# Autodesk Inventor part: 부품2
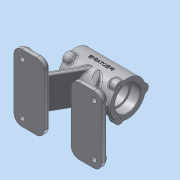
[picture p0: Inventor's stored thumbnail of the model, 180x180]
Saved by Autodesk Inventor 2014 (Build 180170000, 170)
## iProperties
Created: 2026-04
Part Number: 부품2
Material: 알루미늄 6061
Document SubType Name: Modeling
Designer: dg
Density: 2.71 g/cm^3
Appearance: 알루미늄 - 평지
Mass: 749.292 g
Surface Area: 672.069 cm^2
Volume: 276.492 cm^3
Author: dg
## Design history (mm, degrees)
sketch "스케치1"
  geometry: L1 (0, 0)-(-43, 0); L2 (0, 0)-(43, 0); L3 (-43, 0)-(-43, 29); L4 (43, 0)-(43, 29); L5 (-43, 0)-(43, 0); L6 (-43, 29)-(43, 29)
  constraints: 12 end point, 2 collinear, 1 horizontal, 1 perpendicular
  dimensions: "d20" = 43 distance from line of L3 L1.start; "d21" = 43 distance from line of L4 L1.start; "d22" = 58 diameter of L6 L1
revolve "회전3" stored, may be unused: angle "d23" = 90 deg
sketch "스케치4"
  geometry: L1 (0, 0)-(0, 37.954); L2 (0, 23.727)-(-6, 23.727); L3 (-6, 23.727)-(-6, 32); L4 (-6, 32)-(0, 32); L5 (0, 32)-(0, 23.727); L6 (-43, 29)-(43, 29) reference
  constraints: 10 end point, 2 parallel, 1 horizontal, 1 perpendicular, 1 point on line, 1 vertical
  dimensions: "d38" = 3 distance between parallel lines of L6 L4; "d39" = 12 diameter of L3 L1
revolve "회전5" sketch "스케치4" stored, may be unused: angle "d40" = 90 deg
sketch "스케치5" dims "d41" = 52
  geometry: L1 (0, 0)-(0, 40.395); C1 r 22 at (0, 0) reference; C2 r 8 at (0, 26)
  constraints: 2 end point, 1 centre point, 1 coincident, 1 point on line, 1 vertical, 1 vertical alignment, 2 other
  dimensions: "d42" = 16 diameter of C2
extrude "돌출1" join sketch "스케치5" distance "d43" = 10; taper "d44" = 0 deg
fillet "모깎기3" dims "d65" = 3
sketch "스케치8"
  geometry: A1 r 6 centre (0, 0) between (6, 0) and (-6, 0) reference; 1 further point
  constraints: 1 coincident
hole "구멍2" sketch "스케치8" at (0, 0) diameter "d73" = 5.188; stored, may be unused: countersink angle "d77" = 90 deg, drill point angle "d79" = 118 deg; dims "d74" = 18, "d75" = 7, "d76" = 2, "d78" = 20
sketch "스케치9"
  geometry: C1 r 8 at (0, 26); C2 r 21 at (0, 0) reference; A1 r 8 centre (0, 26) between (7.761, 27.942) and (-7.761, 27.942) reference
  constraints: 1 centre point, 1 coincident
extrude "돌출2" join sketch "스케치9" distance "d80" = 10; taper "d81" = -45 deg
sketch "스케치10"
  geometry: L1 (0, 0)-(-43, 0); L2 (0, 0)-(43, 0); L3 (27, 0)-(-27, 0); L4 (-27, 0)-(-27, 18); L5 (-27, 18)-(27, 18); L6 (27, 18)-(27, 0); L7 (-27, 0)-(-43, 0); L8 (-43, 0)-(-43, 21); L9 (-43, 21)-(-27, 21); L10 (-27, 21)-(-27, 0); L11 (27, 0)-(43, 0); L12 (43, 0)-(43, 21); L13 (43, 21)-(27, 21); L14 (27, 21)-(27, 0); L15 (-43, -7.25)-(-43, 27.942) reference; L16 (43, -7.25)-(43, 27.942) reference
  constraints: 28 end point, 7 equal length, 4 horizontal, 3 perpendicular, 1 point on line
  dimensions: "d85" = 43 distance of L1.start L1.end; "d86" = 43 distance of L1.start L2.end; "d87" = 0 distance between parallel lines of L15 L8; "d88" = 0 distance between parallel lines of L16 L12; "d89" = 16 distance between parallel lines of L16 L14; "d90" = 16 distance between parallel lines of L15 L4; "d91" = 36 diameter of L5 L1; "d92" = 42 diameter of L9 L1; "d93" = 42 diameter of L13 L2
revolve "회전7" stored, may be unused: angle "d97" = 90 deg
fillet "모깎기4" dims "d98" = 0.6
chamfer "모따기3" distance "d99" = 1; stored, may be unused: second distance "d100" = 2, angle "d101" = 45 deg
sketch "스케치11"
  geometry: A1 r 8 centre (22.517, -39) between (20.318, -46.692) and (28.079, -33.25) reference; A2 r 8 centre (0, 0) between (7.761, 1.942) and (-7.761, 1.942) reference; A3 r 8 centre (-22.517, -39) between (-28.079, -33.25) and (-20.318, -46.692) reference; 3 further points
  constraints: 3 coincident
hole "구멍3" sketch "스케치11" at (0, 0), (22.517, -39), (-22.517, -39) diameter "d102" = 3.242; stored, may be unused: countersink angle "d106" = 90 deg, drill point angle "d108" = 118 deg; dims "d103" = 8, "d104" = 7, "d105" = 2, "d107" = 10
fillet "모깎기5" dims "d109" = 3
fillet "모깎기6" dims "d110" = 3
node "작업 평면1"
sketch "스케치12"
  geometry: L1 (72, -55)-(22, -55); L2 (22, -55)-(22, 55); L3 (22, 55)-(72, 55); L4 (72, 55)-(72, -55); L5 (-22, -55)-(-72, -55); L6 (-72, -55)-(-72, 55); L7 (-72, 55)-(-22, 55); L8 (-22, 55)-(-22, -55); 1 further point
  constraints: 16 end point, 4 parallel, 2 horizontal, 2 perpendicular
  dimensions: "d112" = 22 distance from line of L2 point (0, 0); "d113" = 22 distance from line of L8 point (0, 0); "d114" = 55 distance from line of L1 point (0, 0); "d115" = 55 distance from line of L3 point (0, 0); "d116" = 55 distance from line of L5 point (0, 0); "d117" = 55 distance from line of L7 point (0, 0); "d118" = 72 distance from line of L4 point (0, 0); "d119" = 72 distance from line of L6 point (0, 0)
extrude "돌출3" join sketch "스케치12" distance "d120" = 9; taper "d121" = 0 deg
sketch "스케치13"
  geometry: L1 (-22, -63)-(-72, -63) reference; L2 (-32, -63)-(5.437, 1.842); L3 (0, 0)-(0, -63.918); L4 (-41.238, -63)-(-3.801, 1.842); L5 (-41.238, -63)-(-32, -63); L6 (5.437, 1.842)-(-3.801, 1.842)
  constraints: 10 end point, 2 parallel, 2 point on line, 1 collinear, 1 perpendicular
  dimensions: "d122" = 30 deg angle of L3 L2; "d123" = 10 distance of L2.start L1.start; "d124" = 8 distance between parallel lines of L2 L4
extrude "돌출4" join sketch "스케치13" stored distance "d125" = 54; taper "d126" = 0 deg
sketch "스케치14"
  geometry: L1 (-41.238, -63)-(-10.975, -10.583) reference; L2 (-22, -63)-(-72, -63) reference; L3 (-41.238, -63)-(-12.569, -13.345); L4 (-55.094, -63)-(-26.425, -13.345); L5 (-55.094, -63)-(-41.238, -63); L6 (-12.569, -13.345)-(-26.425, -13.345); 1 further point
  constraints: 8 end point, 2 parallel, 2 point on line, 1 collinear
  dimensions: "d127" = 12 distance between parallel lines of L1 L4
extrude "돌출5" join sketch "스케치14" stored distance "d128" = 10; taper "d129" = 0 deg
sketch "스케치15"
  geometry: L1 (0, 0)-(-43, 0); L2 (0, 0)-(43, 0); L3 (27, 0)-(-27, 0); L4 (-27, 0)-(-27, 18); L5 (-27, 18)-(27, 18); L6 (27, 18)-(27, 0); L7 (-27, 0)-(-43, 0); L8 (-43, 0)-(-43, 21); L9 (-43, 21)-(-27, 21); L10 (-27, 21)-(-27, 0); L11 (27, 0)-(43, 0); L12 (43, 0)-(43, 21); L13 (43, 21)-(27, 21); L14 (27, 21)-(27, 0); L15 (-43, 22)-(-43, -22) reference; L16 (43, -22)-(43, 22) reference
  constraints: 28 end point, 7 equal length, 4 horizontal, 3 perpendicular, 1 point on line
  dimensions: "d130" = 43 distance of L1.start L1.end; "d131" = 43 distance of L1.start L2.end; "d132" = 0 distance between parallel lines of L16 L12; "d133" = 0 distance between parallel lines of L15 L8; "d134" = 16 distance between parallel lines of L15 L4; "d135" = 16 distance between parallel lines of L16 L14; "d136" = 42 diameter of L9 L1; "d137" = 42 diameter of L13 L2; "d138" = 36 diameter of L5 L2
revolve "회전8" sketch "스케치15" stored, may be unused: angle "d139" = 90 deg
fillet "모깎기7" dims "d140" = 0.6
fillet "모깎기8" dims "d141" = 13
fillet "모깎기9" dims "d142" = 3
fillet "모깎기10" dims "d143" = 3
fillet "모깎기11" dims "d144" = 3
fillet "모깎기12" dims "d145" = 3
sketch "스케치16"
  geometry: C1 r 9 at (59, 42); A1 r 10 centre (59, 42) between (69, 42) and (59, 52) reference; 1 further point
  constraints: 1 centre point, 1 coincident
  dimensions: "d146" = 18 diameter of C1
extrude "돌출6" join sketch "스케치16" distance "d147" = 3; taper "d148" = 0 deg
sketch "스케치17"
  geometry: C1 r 9 at (0, 0) reference; 2 further points
  constraints: 1 coincident
hole "구멍4" sketch "스케치17" at (0, 0) diameter "d149" = 9; stored, may be unused: countersink angle "d153" = 90 deg, drill point angle "d155" = 118 deg; dims "d150" = 8, "d151" = 7, "d152" = 2, "d154" = 10
fillet "모깎기13" dims "d156" = 3
node "작업 평면2"
sketch "스케치18"
  geometry: L1 (35, -72)-(22, -72) reference; 2 further points
  constraints: 1 coincident, 1 other
  dimensions: "d157" = 72 distance from line of L1 point (0, 0)
feature "엠보싱1" sketch "스케치18" dims "d158" = 0.5, "d159" = 0
node "솔리드1"
mirror "대칭1"
mirror "대칭2"
pattern_circular "원형 패턴2" dims angle "d49" = 360 deg
mirror "대칭3"
mirror "대칭5"
mirror "대칭6"
pattern_circular "원형 패턴4" dims angle "d95" = 360 deg
mirror "대칭7"
mirror "대칭8"
mirror "대칭9"
mirror "대칭10"
mirror "대칭11"
mirror "대칭12"
mirror "대칭13"
other parameters: "d111" = -72
